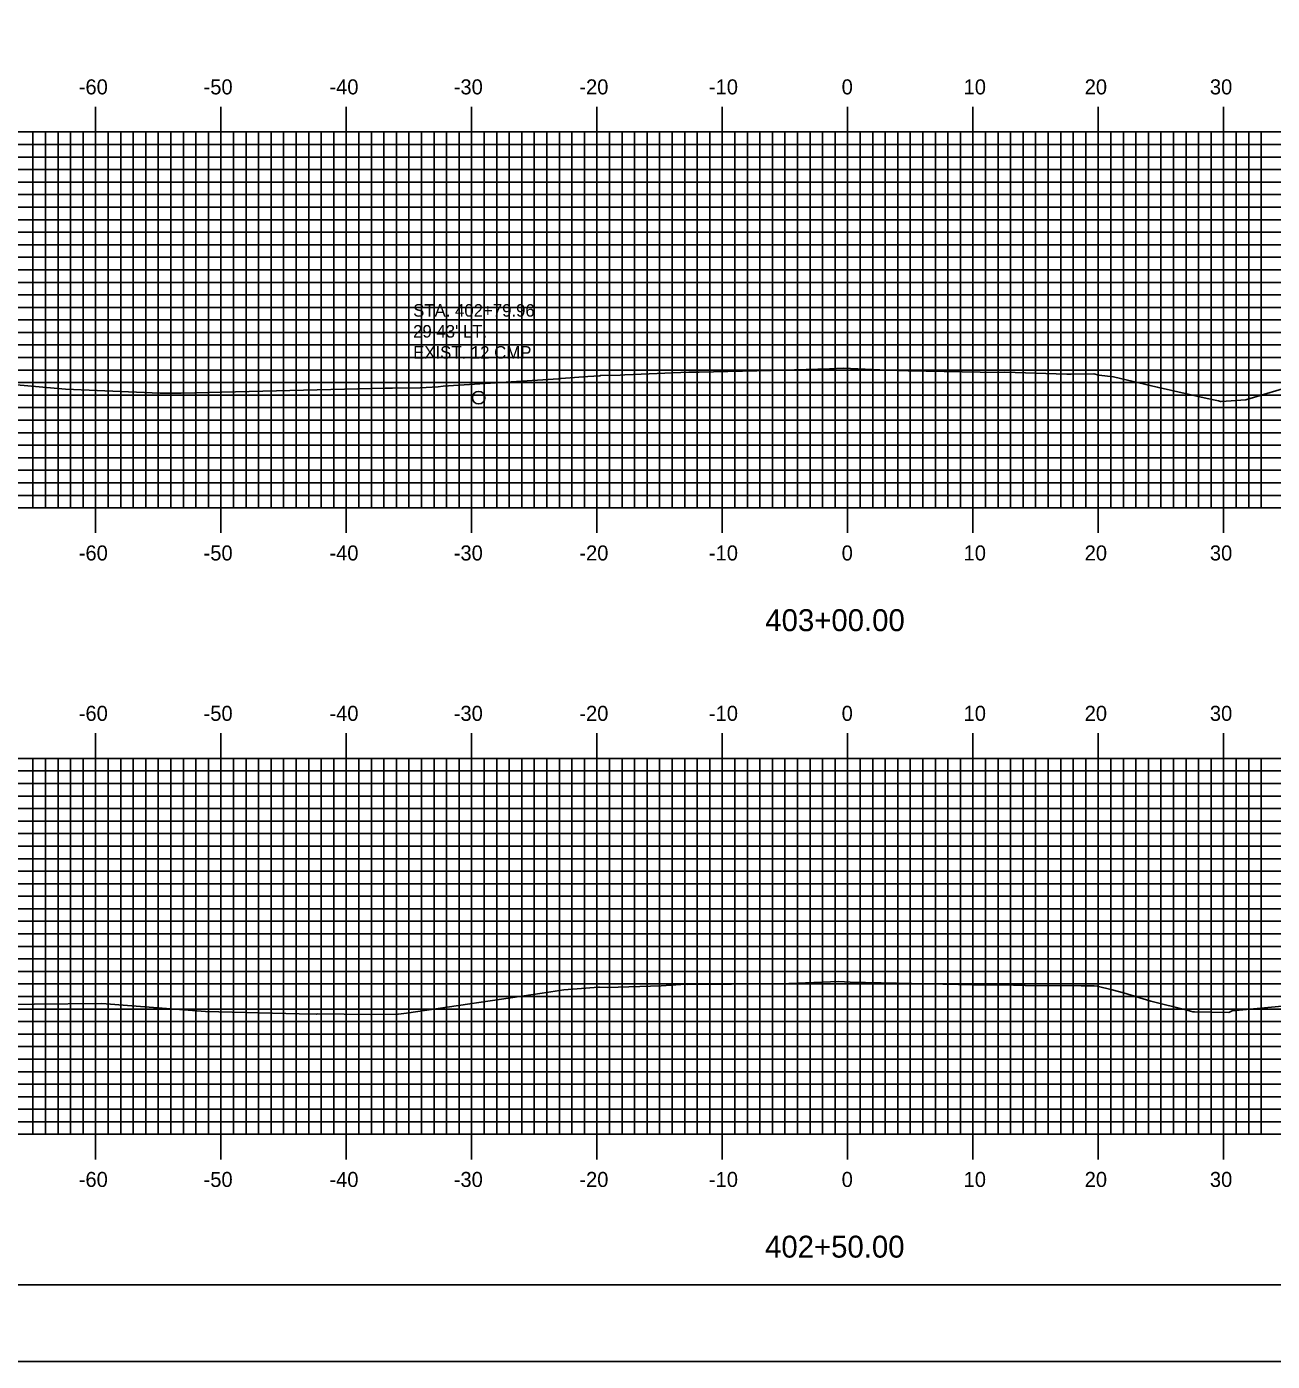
# Model space of a CAD drawing. Extents: x 850955 to 851298, y 364785 to 365005.
# Drawn here: x 851055.2 to 851154.6, y 364785.1 to 364891.6 of the extents above; entities that cross this region are included whole.
import ezdxf

# ---------------------------------------------------------------- set-up
doc = ezdxf.new("R2010")
doc.units = 0
for name, color, linetype in [('BORDER', 7, 'Continuous'), ('D_Drainage_Culvert', 7, 'Continuous'), ('D_Text_Monospaced', 7, 'Continuous'), ('H_V ANNOTATION', 7, 'Continuous'), ('MAJOR', 7, 'Continuous'), ('MINOR', 7, 'Continuous'), ('PLOT BOUNDARY', 7, 'Continuous'), ('S_Roadway_Centerline', 7, 'Continuous')]:
    doc.layers.add(name, color=color, linetype=linetype)

msp = doc.modelspace()

# ---------------------------------------------------------------- linework, layer by layer
at = {"layer": 'BORDER'}
msp.add_lwpolyline([(850971.08, 364791.23), (851291.08, 364791.23), (851291.08, 365001.23), (850971.08, 365001.23)], close=True, dxfattribs=at)
at = {"layer": 'D_Drainage_Culvert'}
msp.add_circle((851091.24, 364862.02), 0.5, dxfattribs=at)
at = {"layer": 'MAJOR'}
for p, q in [((851060.68, 364885.24), (851060.68, 364883.23)), ((851070.68, 364885.24), (851070.68, 364883.23)), ((851080.68, 364885.24), (851080.68, 364883.23)), ((851090.68, 364885.24), (851090.68, 364883.23)), ((851100.68, 364885.24), (851100.68, 364883.23)), ((851110.68, 364885.24), (851110.68, 364883.23)), ((851120.68, 364885.24), (851120.68, 364883.23)), ((851130.68, 364885.24), (851130.68, 364883.23)), ((851140.68, 364885.24), (851140.68, 364883.23)), ((851150.68, 364885.24), (851150.68, 364883.23)), ((850980.68, 364883.23), (851260.68, 364883.23)), ((850980.68, 364883.23), (851260.68, 364883.23)), ((851060.68, 364853.23), (851060.68, 364883.23)), ((851070.68, 364853.23), (851070.68, 364883.23)), ((851080.68, 364853.23), (851080.68, 364883.23)), ((851090.68, 364853.23), (851090.68, 364883.23)), ((851100.68, 364853.23), (851100.68, 364883.23)), ((851110.68, 364853.23), (851110.68, 364883.23)), ((851120.68, 364853.23), (851120.68, 364883.23)), ((851130.68, 364853.23), (851130.68, 364883.23)), ((851140.68, 364853.23), (851140.68, 364883.23)), ((851150.68, 364853.23), (851150.68, 364883.23)), ((850980.68, 364878.23), (851260.68, 364878.23)), ((850980.68, 364873.23), (851260.68, 364873.23)), ((850980.68, 364868.23), (851260.68, 364868.23)), ((850980.68, 364863.23), (851260.68, 364863.23)), ((850980.68, 364858.23), (851260.68, 364858.23)), ((850980.68, 364853.23), (851260.68, 364853.23)), ((850980.68, 364853.23), (851260.68, 364853.23)), ((851060.68, 364851.23), (851060.68, 364853.23)), ((851070.68, 364851.23), (851070.68, 364853.23)), ((851080.68, 364851.23), (851080.68, 364853.23)), ((851090.68, 364851.23), (851090.68, 364853.23)), ((851100.68, 364851.23), (851100.68, 364853.23)), ((851110.68, 364851.23), (851110.68, 364853.23)), ((851120.68, 364851.23), (851120.68, 364853.23)), ((851130.68, 364851.23), (851130.68, 364853.23)), ((851140.68, 364851.23), (851140.68, 364853.23)), ((851150.68, 364851.23), (851150.68, 364853.23)), ((851060.68, 364835.24), (851060.68, 364833.23)), ((851070.68, 364835.24), (851070.68, 364833.23)), ((851080.68, 364835.24), (851080.68, 364833.23)), ((851090.68, 364835.24), (851090.68, 364833.23)), ((851100.68, 364835.24), (851100.68, 364833.23)), ((851110.68, 364835.24), (851110.68, 364833.23)), ((851120.68, 364835.24), (851120.68, 364833.23)), ((851130.68, 364835.24), (851130.68, 364833.23)), ((851140.68, 364835.24), (851140.68, 364833.23)), ((851150.68, 364835.24), (851150.68, 364833.23)), ((850980.68, 364833.23), (851260.68, 364833.23)), ((850980.68, 364833.23), (851260.68, 364833.23)), ((851060.68, 364803.23), (851060.68, 364833.23)), ((851070.68, 364803.23), (851070.68, 364833.23)), ((851080.68, 364803.23), (851080.68, 364833.23)), ((851090.68, 364803.23), (851090.68, 364833.23)), ((851100.68, 364803.23), (851100.68, 364833.23)), ((851110.68, 364803.23), (851110.68, 364833.23)), ((851120.68, 364803.23), (851120.68, 364833.23)), ((851130.68, 364803.23), (851130.68, 364833.23)), ((851140.68, 364803.23), (851140.68, 364833.23)), ((851150.68, 364803.23), (851150.68, 364833.23)), ((850980.68, 364828.23), (851260.68, 364828.23)), ((850980.68, 364823.23), (851260.68, 364823.23)), ((850980.68, 364818.23), (851260.68, 364818.23)), ((850980.68, 364813.23), (851260.68, 364813.23)), ((850980.68, 364808.23), (851260.68, 364808.23)), ((850980.68, 364803.23), (851260.68, 364803.23)), ((850980.68, 364803.23), (851260.68, 364803.23)), ((851060.68, 364801.23), (851060.68, 364803.23)), ((851070.68, 364801.23), (851070.68, 364803.23)), ((851080.68, 364801.23), (851080.68, 364803.23)), ((851090.68, 364801.23), (851090.68, 364803.23)), ((851100.68, 364801.23), (851100.68, 364803.23)), ((851110.68, 364801.23), (851110.68, 364803.23)), ((851120.68, 364801.23), (851120.68, 364803.23)), ((851130.68, 364801.23), (851130.68, 364803.23)), ((851140.68, 364801.23), (851140.68, 364803.23)), ((851150.68, 364801.23), (851150.68, 364803.23))]:
    msp.add_line(p, q, dxfattribs=at)
at = {"layer": 'MINOR'}
for p, q in [((851055.68, 364853.23), (851055.68, 364883.23)), ((851056.68, 364853.23), (851056.68, 364883.23)), ((851057.68, 364853.23), (851057.68, 364883.23)), ((851058.68, 364853.23), (851058.68, 364883.23)), ((851059.68, 364853.23), (851059.68, 364883.23)), ((851061.68, 364853.23), (851061.68, 364883.23)), ((851062.68, 364853.23), (851062.68, 364883.23)), ((851063.68, 364853.23), (851063.68, 364883.23)), ((851064.68, 364853.23), (851064.68, 364883.23)), ((851065.68, 364853.23), (851065.68, 364883.23)), ((851066.68, 364853.23), (851066.68, 364883.23)), ((851067.68, 364853.23), (851067.68, 364883.23)), ((851068.68, 364853.23), (851068.68, 364883.23)), ((851069.68, 364853.23), (851069.68, 364883.23)), ((851071.68, 364853.23), (851071.68, 364883.23)), ((851072.68, 364853.23), (851072.68, 364883.23)), ((851073.68, 364853.23), (851073.68, 364883.23)), ((851074.68, 364853.23), (851074.68, 364883.23)), ((851075.68, 364853.23), (851075.68, 364883.23)), ((851076.68, 364853.23), (851076.68, 364883.23)), ((851077.68, 364853.23), (851077.68, 364883.23)), ((851078.68, 364853.23), (851078.68, 364883.23)), ((851079.68, 364853.23), (851079.68, 364883.23)), ((851081.68, 364853.23), (851081.68, 364883.23)), ((851082.68, 364853.23), (851082.68, 364883.23)), ((851083.68, 364853.23), (851083.68, 364883.23)), ((851084.68, 364853.23), (851084.68, 364883.23)), ((851085.68, 364853.23), (851085.68, 364883.23)), ((851086.68, 364853.23), (851086.68, 364883.23)), ((851087.68, 364853.23), (851087.68, 364883.23)), ((851088.68, 364853.23), (851088.68, 364883.23)), ((851089.68, 364853.23), (851089.68, 364883.23)), ((851091.68, 364853.23), (851091.68, 364883.23)), ((851092.68, 364853.23), (851092.68, 364883.23)), ((851093.68, 364853.23), (851093.68, 364883.23)), ((851094.68, 364853.23), (851094.68, 364883.23)), ((851095.68, 364853.23), (851095.68, 364883.23)), ((851096.68, 364853.23), (851096.68, 364883.23)), ((851097.68, 364853.23), (851097.68, 364883.23)), ((851098.68, 364853.23), (851098.68, 364883.23)), ((851099.68, 364853.23), (851099.68, 364883.23)), ((851101.68, 364853.23), (851101.68, 364883.23)), ((851102.68, 364853.23), (851102.68, 364883.23)), ((851103.68, 364853.23), (851103.68, 364883.23)), ((851104.68, 364853.23), (851104.68, 364883.23)), ((851105.68, 364853.23), (851105.68, 364883.23)), ((851106.68, 364853.23), (851106.68, 364883.23)), ((851107.68, 364853.23), (851107.68, 364883.23)), ((851108.68, 364853.23), (851108.68, 364883.23)), ((851109.68, 364853.23), (851109.68, 364883.23)), ((851111.68, 364853.23), (851111.68, 364883.23)), ((851112.68, 364853.23), (851112.68, 364883.23)), ((851113.68, 364853.23), (851113.68, 364883.23)), ((851114.68, 364853.23), (851114.68, 364883.23)), ((851115.68, 364853.23), (851115.68, 364883.23)), ((851116.68, 364853.23), (851116.68, 364883.23)), ((851117.68, 364853.23), (851117.68, 364883.23)), ((851118.68, 364853.23), (851118.68, 364883.23)), ((851119.68, 364853.23), (851119.68, 364883.23)), ((851121.68, 364853.23), (851121.68, 364883.23)), ((851122.68, 364853.23), (851122.68, 364883.23)), ((851123.68, 364853.23), (851123.68, 364883.23)), ((851124.68, 364853.23), (851124.68, 364883.23)), ((851125.68, 364853.23), (851125.68, 364883.23)), ((851126.68, 364853.23), (851126.68, 364883.23)), ((851127.68, 364853.23), (851127.68, 364883.23)), ((851128.68, 364853.23), (851128.68, 364883.23)), ((851129.68, 364853.23), (851129.68, 364883.23)), ((851131.68, 364853.23), (851131.68, 364883.23)), ((851132.68, 364853.23), (851132.68, 364883.23)), ((851133.68, 364853.23), (851133.68, 364883.23)), ((851134.68, 364853.23), (851134.68, 364883.23)), ((851135.68, 364853.23), (851135.68, 364883.23)), ((851136.68, 364853.23), (851136.68, 364883.23)), ((851137.68, 364853.23), (851137.68, 364883.23)), ((851138.68, 364853.23), (851138.68, 364883.23)), ((851139.68, 364853.23), (851139.68, 364883.23)), ((851141.68, 364853.23), (851141.68, 364883.23)), ((851142.68, 364853.23), (851142.68, 364883.23)), ((851143.68, 364853.23), (851143.68, 364883.23)), ((851144.68, 364853.23), (851144.68, 364883.23)), ((851145.68, 364853.23), (851145.68, 364883.23)), ((851146.68, 364853.23), (851146.68, 364883.23)), ((851147.68, 364853.23), (851147.68, 364883.23)), ((851148.68, 364853.23), (851148.68, 364883.23)), ((851149.68, 364853.23), (851149.68, 364883.23)), ((851151.68, 364853.23), (851151.68, 364883.23)), ((851152.68, 364853.23), (851152.68, 364883.23)), ((851153.68, 364853.23), (851153.68, 364883.23)), ((850980.68, 364882.23), (851260.68, 364882.23)), ((850980.68, 364881.23), (851260.68, 364881.23)), ((850980.68, 364880.23), (851260.68, 364880.23)), ((850980.68, 364879.23), (851260.68, 364879.23)), ((850980.68, 364877.23), (851260.68, 364877.23)), ((850980.68, 364876.23), (851260.68, 364876.23)), ((850980.68, 364875.23), (851260.68, 364875.23)), ((850980.68, 364874.23), (851260.68, 364874.23)), ((850980.68, 364872.23), (851260.68, 364872.23)), ((850980.68, 364871.23), (851260.68, 364871.23)), ((850980.68, 364870.23), (851260.68, 364870.23)), ((850980.68, 364869.23), (851260.68, 364869.23)), ((850980.68, 364867.23), (851260.68, 364867.23)), ((850980.68, 364866.23), (851260.68, 364866.23)), ((850980.68, 364865.23), (851260.68, 364865.23)), ((850980.68, 364864.23), (851260.68, 364864.23)), ((850980.68, 364862.23), (851260.68, 364862.23)), ((850980.68, 364861.23), (851260.68, 364861.23)), ((850980.68, 364860.23), (851260.68, 364860.23)), ((850980.68, 364859.23), (851260.68, 364859.23)), ((850980.68, 364857.23), (851260.68, 364857.23)), ((850980.68, 364856.23), (851260.68, 364856.23)), ((850980.68, 364855.23), (851260.68, 364855.23)), ((850980.68, 364854.23), (851260.68, 364854.23)), ((851055.68, 364803.23), (851055.68, 364833.23)), ((851056.68, 364803.23), (851056.68, 364833.23)), ((851057.68, 364803.23), (851057.68, 364833.23)), ((851058.68, 364803.23), (851058.68, 364833.23)), ((851059.68, 364803.23), (851059.68, 364833.23)), ((851061.68, 364803.23), (851061.68, 364833.23)), ((851062.68, 364803.23), (851062.68, 364833.23)), ((851063.68, 364803.23), (851063.68, 364833.23)), ((851064.68, 364803.23), (851064.68, 364833.23)), ((851065.68, 364803.23), (851065.68, 364833.23)), ((851066.68, 364803.23), (851066.68, 364833.23)), ((851067.68, 364803.23), (851067.68, 364833.23)), ((851068.68, 364803.23), (851068.68, 364833.23)), ((851069.68, 364803.23), (851069.68, 364833.23)), ((851071.68, 364803.23), (851071.68, 364833.23)), ((851072.68, 364803.23), (851072.68, 364833.23)), ((851073.68, 364803.23), (851073.68, 364833.23)), ((851074.68, 364803.23), (851074.68, 364833.23)), ((851075.68, 364803.23), (851075.68, 364833.23)), ((851076.68, 364803.23), (851076.68, 364833.23)), ((851077.68, 364803.23), (851077.68, 364833.23)), ((851078.68, 364803.23), (851078.68, 364833.23)), ((851079.68, 364803.23), (851079.68, 364833.23)), ((851081.68, 364803.23), (851081.68, 364833.23)), ((851082.68, 364803.23), (851082.68, 364833.23)), ((851083.68, 364803.23), (851083.68, 364833.23)), ((851084.68, 364803.23), (851084.68, 364833.23)), ((851085.68, 364803.23), (851085.68, 364833.23)), ((851086.68, 364803.23), (851086.68, 364833.23)), ((851087.68, 364803.23), (851087.68, 364833.23)), ((851088.68, 364803.23), (851088.68, 364833.23)), ((851089.68, 364803.23), (851089.68, 364833.23)), ((851091.68, 364803.23), (851091.68, 364833.23)), ((851092.68, 364803.23), (851092.68, 364833.23)), ((851093.68, 364803.23), (851093.68, 364833.23)), ((851094.68, 364803.23), (851094.68, 364833.23)), ((851095.68, 364803.23), (851095.68, 364833.23)), ((851096.68, 364803.23), (851096.68, 364833.23)), ((851097.68, 364803.23), (851097.68, 364833.23)), ((851098.68, 364803.23), (851098.68, 364833.23)), ((851099.68, 364803.23), (851099.68, 364833.23)), ((851101.68, 364803.23), (851101.68, 364833.23)), ((851102.68, 364803.23), (851102.68, 364833.23)), ((851103.68, 364803.23), (851103.68, 364833.23)), ((851104.68, 364803.23), (851104.68, 364833.23)), ((851105.68, 364803.23), (851105.68, 364833.23)), ((851106.68, 364803.23), (851106.68, 364833.23)), ((851107.68, 364803.23), (851107.68, 364833.23)), ((851108.68, 364803.23), (851108.68, 364833.23)), ((851109.68, 364803.23), (851109.68, 364833.23)), ((851111.68, 364803.23), (851111.68, 364833.23)), ((851112.68, 364803.23), (851112.68, 364833.23)), ((851113.68, 364803.23), (851113.68, 364833.23)), ((851114.68, 364803.23), (851114.68, 364833.23)), ((851115.68, 364803.23), (851115.68, 364833.23)), ((851116.68, 364803.23), (851116.68, 364833.23)), ((851117.68, 364803.23), (851117.68, 364833.23)), ((851118.68, 364803.23), (851118.68, 364833.23)), ((851119.68, 364803.23), (851119.68, 364833.23)), ((851121.68, 364803.23), (851121.68, 364833.23)), ((851122.68, 364803.23), (851122.68, 364833.23)), ((851123.68, 364803.23), (851123.68, 364833.23)), ((851124.68, 364803.23), (851124.68, 364833.23)), ((851125.68, 364803.23), (851125.68, 364833.23)), ((851126.68, 364803.23), (851126.68, 364833.23)), ((851127.68, 364803.23), (851127.68, 364833.23)), ((851128.68, 364803.23), (851128.68, 364833.23)), ((851129.68, 364803.23), (851129.68, 364833.23)), ((851131.68, 364803.23), (851131.68, 364833.23)), ((851132.68, 364803.23), (851132.68, 364833.23)), ((851133.68, 364803.23), (851133.68, 364833.23)), ((851134.68, 364803.23), (851134.68, 364833.23)), ((851135.68, 364803.23), (851135.68, 364833.23)), ((851136.68, 364803.23), (851136.68, 364833.23)), ((851137.68, 364803.23), (851137.68, 364833.23)), ((851138.68, 364803.23), (851138.68, 364833.23)), ((851139.68, 364803.23), (851139.68, 364833.23)), ((851141.68, 364803.23), (851141.68, 364833.23)), ((851142.68, 364803.23), (851142.68, 364833.23)), ((851143.68, 364803.23), (851143.68, 364833.23)), ((851144.68, 364803.23), (851144.68, 364833.23)), ((851145.68, 364803.23), (851145.68, 364833.23)), ((851146.68, 364803.23), (851146.68, 364833.23)), ((851147.68, 364803.23), (851147.68, 364833.23)), ((851148.68, 364803.23), (851148.68, 364833.23)), ((851149.68, 364803.23), (851149.68, 364833.23)), ((851151.68, 364803.23), (851151.68, 364833.23)), ((851152.68, 364803.23), (851152.68, 364833.23)), ((851153.68, 364803.23), (851153.68, 364833.23)), ((850980.68, 364832.23), (851260.68, 364832.23)), ((850980.68, 364831.23), (851260.68, 364831.23)), ((850980.68, 364830.23), (851260.68, 364830.23)), ((850980.68, 364829.23), (851260.68, 364829.23)), ((850980.68, 364827.23), (851260.68, 364827.23)), ((850980.68, 364826.23), (851260.68, 364826.23)), ((850980.68, 364825.23), (851260.68, 364825.23)), ((850980.68, 364824.23), (851260.68, 364824.23)), ((850980.68, 364822.23), (851260.68, 364822.23)), ((850980.68, 364821.23), (851260.68, 364821.23)), ((850980.68, 364820.23), (851260.68, 364820.23)), ((850980.68, 364819.23), (851260.68, 364819.23)), ((850980.68, 364817.23), (851260.68, 364817.23)), ((850980.68, 364816.23), (851260.68, 364816.23)), ((850980.68, 364815.23), (851260.68, 364815.23)), ((850980.68, 364814.23), (851260.68, 364814.23)), ((850980.68, 364812.23), (851260.68, 364812.23)), ((850980.68, 364811.23), (851260.68, 364811.23)), ((850980.68, 364810.23), (851260.68, 364810.23)), ((850980.68, 364809.23), (851260.68, 364809.23)), ((850980.68, 364807.23), (851260.68, 364807.23)), ((850980.68, 364806.23), (851260.68, 364806.23)), ((850980.68, 364805.23), (851260.68, 364805.23)), ((850980.68, 364804.23), (851260.68, 364804.23))]:
    msp.add_line(p, q, dxfattribs=at)
at = {"layer": 'PLOT BOUNDARY'}
msp.add_lwpolyline([(850954.89, 364785.11), (851294.89, 364785.11), (851294.89, 365005.11), (850954.89, 365005.11)], close=True, dxfattribs=at)
at = {"layer": 'S_Roadway_Centerline'}
for points in [[(851054.36, 364863.04), (851058.28, 364862.7), (851065.83, 364862.39), (851067.5, 364862.39), (851083.78, 364862.78), (851084.04, 364862.78), (851084.14, 364862.78), (851084.2, 364862.78), (851084.33, 364862.79), (851084.37, 364862.79), (851086.56, 364862.82), (851088, 364862.89), (851088.41, 364862.93), (851097.6, 364863.54), (851097.64, 364863.55), (851097.81, 364863.55), (851099.96, 364863.72), (851100.9, 364863.78), (851100.97, 364863.79), (851102.54, 364863.82), (851102.9, 364863.84), (851103.56, 364863.87), (851108.01, 364864.06), (851108.82, 364864.06), (851114.58, 364864.2), (851119.24, 364864.32), (851120.33, 364864.39), (851123.82, 364864.22), (851125.52, 364864.18), (851132.69, 364864.04), (851133.22, 364864.07), (851137.32, 364863.93), (851138.16, 364863.9), (851138.51, 364863.91), (851140.31, 364863.92), (851140.73, 364863.83), (851141.88, 364863.69), (851145.38, 364862.87), (851145.58, 364862.82), (851145.63, 364862.82), (851145.85, 364862.76), (851149.36, 364861.96), (851150.27, 364861.76), (851150.43, 364861.71), (851150.47, 364861.71), (851152.44, 364861.84), (851152.54, 364861.87), (851156.45, 364863.05)], [(851050.35, 364813.57), (851061.18, 364813.68), (851061.51, 364813.65), (851063.21, 364813.52), (851069.45, 364813.03), (851076.92, 364812.85), (851078.28, 364812.81), (851078.42, 364812.84), (851082.6, 364812.8), (851084.79, 364812.81), (851084.83, 364812.81), (851085.48, 364812.91), (851096.3, 364814.5), (851098.03, 364814.77), (851099.09, 364814.84), (851100.8, 364814.97), (851100.87, 364814.98), (851101.53, 364814.94), (851105.81, 364815.08), (851107.76, 364815.21), (851107.89, 364815.2), (851114.95, 364815.25), (851115.98, 364815.26), (851119.98, 364815.42), (851120.87, 364815.37), (851130.75, 364815.17), (851132.68, 364815.14), (851132.98, 364815.15), (851134.85, 364815.1), (851139.3, 364815.07), (851140.36, 364815.08), (851140.6, 364815.05), (851141.78, 364814.75), (851142.7, 364814.51), (851144.86, 364813.87), (851147.76, 364813.13), (851148.03, 364813.07), (851148.21, 364813.01), (851148.34, 364813.01), (851151.1, 364812.95), (851151.37, 364813.08), (851156.48, 364813.57)]]:
    msp.add_lwpolyline(points, dxfattribs=at)

# ---------------------------------------------------------------- texts
at = {"layer": 'D_Text_Monospaced'}
for s, p in [('STA. 402+79.96', (851086.01, 364868.49)), ("29.43' LT.", (851086.01, 364866.82)), ('EXIST. 12 CMP', (851086.01, 364865.14))]:
    msp.add_text(s, height=1, dxfattribs=at).set_placement(p)
at = {"layer": 'H_V ANNOTATION'}
for s, height, p in [('-60', 1.2, (851059.33, 364886.23)), ('-50', 1.2, (851069.29, 364886.23)), ('-40', 1.2, (851079.33, 364886.23)), ('-30', 1.2, (851089.25, 364886.23)), ('-20', 1.2, (851099.27, 364886.23)), ('-10', 1.2, (851109.61, 364886.23)), ('0', 1.2, (851120.2, 364886.23)), ('10', 1.2, (851129.93, 364886.23)), ('20', 1.2, (851139.59, 364886.23)), ('30', 1.2, (851149.58, 364886.23)), ('-60', 1.2, (851059.33, 364849.03)), ('-50', 1.2, (851069.29, 364849.03)), ('-40', 1.2, (851079.33, 364849.03)), ('-30', 1.2, (851089.25, 364849.03)), ('-20', 1.2, (851099.27, 364849.03)), ('-10', 1.2, (851109.61, 364849.03)), ('0', 1.2, (851120.2, 364849.03)), ('10', 1.2, (851129.93, 364849.03)), ('20', 1.2, (851139.59, 364849.03)), ('30', 1.2, (851149.58, 364849.03)), ('403+00.00', 1.75, (851114.11, 364843.39)), ('-60', 1.2, (851059.33, 364836.23)), ('-50', 1.2, (851069.29, 364836.23)), ('-40', 1.2, (851079.33, 364836.23)), ('-30', 1.2, (851089.25, 364836.23)), ('-20', 1.2, (851099.27, 364836.23)), ('-10', 1.2, (851109.61, 364836.23)), ('0', 1.2, (851120.2, 364836.23)), ('10', 1.2, (851129.93, 364836.23)), ('20', 1.2, (851139.59, 364836.23)), ('30', 1.2, (851149.58, 364836.23)), ('-60', 1.2, (851059.33, 364799.03)), ('-50', 1.2, (851069.29, 364799.03)), ('-40', 1.2, (851079.33, 364799.03)), ('-30', 1.2, (851089.25, 364799.03)), ('-20', 1.2, (851099.27, 364799.03)), ('-10', 1.2, (851109.61, 364799.03)), ('0', 1.2, (851120.2, 364799.03)), ('10', 1.2, (851129.93, 364799.03)), ('20', 1.2, (851139.59, 364799.03)), ('30', 1.2, (851149.58, 364799.03)), ('402+50.00', 1.75, (851114.09, 364793.39))]:
    msp.add_text(s, height=height, dxfattribs=at).set_placement(p)
at = {"layer": 'S_Roadway_Centerline'}
for s, p in [('L', (851120.32, 364864.39)), ('C', (851120.33, 364864.39)), ('C', (851119.97, 364815.42)), ('L', (851119.97, 364815.41))]:
    msp.add_text(s, height=0.0146, dxfattribs=at).set_placement(p)

doc.saveas('drawing.dxf')
